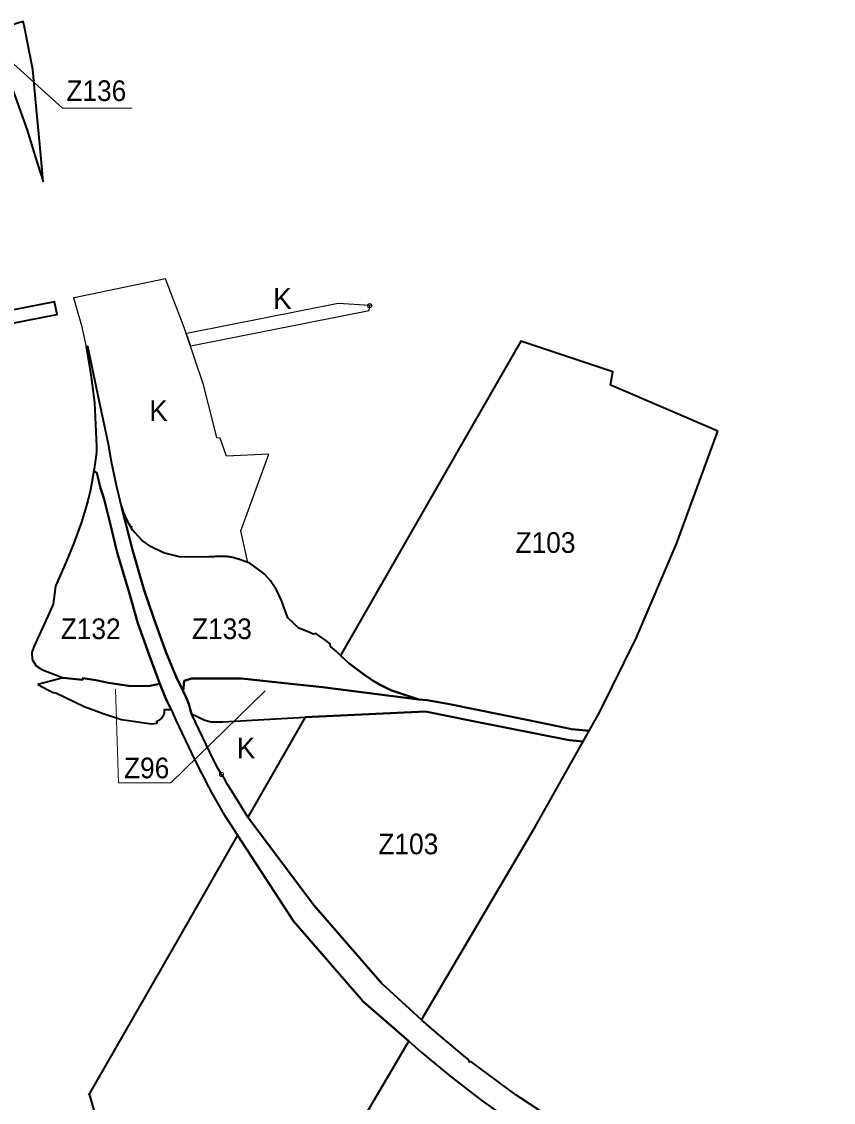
# Model space of a CAD drawing. Extents: x -650276 to -642489, y -1074311 to -1066658.
# Drawn here: x -647869 to -646927, y -1068210 to -1066956 of the extents above; entities that cross this region are included whole.
import ezdxf

# ---------------------------------------------------------------- set-up
doc = ezdxf.new("R2010")
doc.units = 0
doc.header["$LTSCALE"] = 9.6
doc.header["$PDMODE"] = 32
doc.header["$PDSIZE"] = 4.8
for name, color, linetype, lineweight in [('4', 7, 'Continuous', 40), ('41', 7, 'Continuous', 25), ('44', 7, 'Continuous', 40), ('45', 7, 'Continuous', 40), ('46', 7, 'Continuous', 13), ('47', 7, 'Continuous', 13), ('48', 7, 'Continuous', 35), ('59', 7, 'Continuous', 13)]:
    doc.layers.add(name, color=color, linetype=linetype, lineweight=lineweight)
doc.layers.add('43', color=7, linetype='Continuous')

msp = doc.modelspace()

# ---------------------------------------------------------------- linework, layer by layer
at = {"layer": '4'}
msp.add_lwpolyline([(-647876.57, -1067043.5), (-647863.04, -1067081.36), (-647853.65, -1067111.91), (-647844.3, -1067141.25), (-647847.09, -1067110.58), (-647850.07, -1067077.71), (-647852.63, -1067049.52), (-647856.11, -1067011.21), (-647866.14, -1066961.98), (-647867.46, -1066955.52), (-647905.28, -1066967.07), (-647903.5, -1066972.05)], close=True, dxfattribs=at)
at = {"layer": '41'}
for p, q in [((-647740.124, -1067546.265), (-647739.417, -1067547.032)), ((-647740, -1067546.181), (-647739.998, -1067546.18)), ((-647640.591, -1067576.33), (-647640.087, -1067576.306))]:
    msp.add_line(p, q, dxfattribs=at)
for points in [[(-647638.68, -1067439.06), (-647642.686, -1067438.46), (-647645.78, -1067425.81), (-647658.13, -1067376.99), (-647680.64, -1067310.37), (-647702.42, -1067253.98), (-647808.25, -1067276.11), (-647809.02, -1067276.27), (-647804.823, -1067290.788)], [(-647465.203, -1067285.115), (-647501.968, -1067282.642), (-647673.685, -1067316.666), (-647678.21, -1067317.562), (-647673.367, -1067331.895), (-647670.77, -1067331.38), (-647501.099, -1067297.762)], [(-647501.099, -1067297.762), (-647465.699, -1067290.747), (-647465.203, -1067285.115)], [(-647804.823, -1067290.788), (-647799.76, -1067308.3), (-647794.54, -1067333.14)], [(-647794.54, -1067333.14), (-647792.52, -1067332.74), (-647778.78, -1067397.1), (-647768.5, -1067446.04)], [(-647768.5, -1067446.04), (-647764.89, -1067466.64), (-647759.16, -1067494.01), (-647756.55, -1067505.32), (-647755.255, -1067510.676)], [(-647615.048, -1067580.385), (-647606.559, -1067583.309), (-647614.75, -1067546.53), (-647582.2, -1067457.65), (-647631.59, -1067459.72), (-647638.68, -1067439.06)], [(-647755.255, -1067510.676), (-647755.159, -1067511.027), (-647754.116, -1067514.604)], [(-647754.116, -1067514.604), (-647753.006, -1067518.156), (-647751.818, -1067521.68), (-647750.545, -1067525.169), (-647749.178, -1067528.619), (-647747.708, -1067532.022), (-647746.127, -1067535.371), (-647744.43, -1067538.658), (-647740.122, -1067546.264)], [(-647742.158, -1067541.404), (-647741.902, -1067541.247), (-647741.647, -1067541.09), (-647740.804, -1067541.512), (-647742.167, -1067542.348)], [(-647739.998, -1067546.18), (-647742.045, -1067542.565), (-647742.167, -1067542.348), (-647742.158, -1067541.404)], [(-647742.167, -1067542.348), (-647742.037, -1067542.56), (-647741.936, -1067542.723), (-647741.743, -1067543.03), (-647741.67, -1067543.146), (-647741.447, -1067543.497), (-647741.402, -1067543.568), (-647741.148, -1067543.963), (-647741.132, -1067543.989), (-647740.859, -1067544.408), (-647740.846, -1067544.427), (-647740.583, -1067544.825), (-647740.541, -1067544.889), (-647740.519, -1067544.919), (-647740.333, -1067545.195), (-647740.265, -1067545.295), (-647740.068, -1067545.582), (-647739.971, -1067545.724), (-647739.801, -1067545.968), (-647739.674, -1067546.15), (-647739.532, -1067546.353), (-647739.504, -1067546.391), (-647739.374, -1067546.575), (-647739.26, -1067546.736), (-647739.072, -1067546.998), (-647738.986, -1067547.117), (-647738.767, -1067547.418), (-647738.709, -1067547.496), (-647738.456, -1067547.839), (-647738.431, -1067547.874), (-647738.148, -1067548.252), (-647737.867, -1067548.624), (-647737.834, -1067548.667), (-647737.581, -1067548.996), (-647737.518, -1067549.078)], [(-647739.966, -1067546.23), (-647739.968, -1067546.231), (-647739.983, -1067546.206)], [(-647737.525, -1067549.085), (-647729.802, -1067557.462), (-647719.661, -1067564.884), (-647704.458, -1067572.034), (-647685.968, -1067576.68)], [(-647685.968, -1067576.68), (-647654.743, -1067576.996), (-647651.965, -1067576.865)], [(-647651.965, -1067576.865), (-647651.711, -1067576.853), (-647651.205, -1067576.828), (-647650.7, -1067576.803), (-647650.194, -1067576.778), (-647649.689, -1067576.752), (-647649.183, -1067576.727), (-647648.677, -1067576.701), (-647648.172, -1067576.675), (-647647.897, -1067576.661), (-647647.666, -1067576.65), (-647647.161, -1067576.624), (-647646.655, -1067576.598), (-647646.149, -1067576.572), (-647645.644, -1067576.546), (-647645.138, -1067576.521), (-647644.899, -1067576.509), (-647644.633, -1067576.496), (-647644.127, -1067576.471), (-647643.622, -1067576.447), (-647643.117, -1067576.424), (-647642.611, -1067576.401), (-647642.106, -1067576.38), (-647641.901, -1067576.371), (-647641.601, -1067576.359), (-647641.096, -1067576.34), (-647640.592, -1067576.322)], [(-647640.087, -1067576.306), (-647639.583, -1067576.291), (-647639.078, -1067576.278), (-647638.902, -1067576.275), (-647638.574, -1067576.267), (-647638.071, -1067576.258), (-647637.567, -1067576.251), (-647637.064, -1067576.246), (-647637.01, -1067576.246), (-647636.419, -1067576.254), (-647635.902, -1067576.265), (-647635.757, -1067576.268), (-647635.094, -1067576.286), (-647635.037, -1067576.288), (-647634.431, -1067576.309), (-647633.767, -1067576.337), (-647633.102, -1067576.37), (-647633.058, -1067576.372), (-647632.9, -1067576.382), (-647632.437, -1067576.408), (-647631.772, -1067576.452), (-647631.106, -1067576.502), (-647631.076, -1067576.504), (-647630.44, -1067576.557), (-647629.896, -1067576.607), (-647629.774, -1067576.618), (-647629.107, -1067576.685), (-647629.091, -1067576.687), (-647628.441, -1067576.759), (-647627.775, -1067576.839), (-647627.107, -1067576.926), (-647626.443, -1067577.019), (-647625.783, -1067577.139), (-647625.14, -1067577.282), (-647625.129, -1067577.284), (-647624.476, -1067577.436), (-647623.824, -1067577.594), (-647623.199, -1067577.752), (-647623.174, -1067577.759), (-647622.525, -1067577.929), (-647621.877, -1067578.106), (-647621.269, -1067578.278), (-647621.23, -1067578.289), (-647620.586, -1067578.478), (-647619.942, -1067578.674), (-647619.352, -1067578.859), (-647619.301, -1067578.875), (-647618.661, -1067579.083), (-647618.023, -1067579.297), (-647617.451, -1067579.494), (-647617.387, -1067579.517), (-647616.752, -1067579.743), (-647616.12, -1067579.975), (-647615.566, -1067580.184), (-647615.489, -1067580.214), (-647615.048, -1067580.385)]]:
    msp.add_lwpolyline(points, dxfattribs=at)
for start, end in [(214.04927, 214.0695), (214.08975, 214.75472)]:
    msp.add_arc((-647670.608, -1067499.289), 83.75, start, end, dxfattribs=at)
msp.add_point((-647465.203, -1067285.115), dxfattribs=at)
at = {"layer": '44'}
for p, q in [((-647489.3, -1067700.07), (-647474.13, -1067711.81)), ((-647540.208, -1067762.876), (-647400.63, -1067756.19))]:
    msp.add_line(p, q, dxfattribs=at)
for points in [[(-647606.818, -1067879.061), (-647617.25, -1067861.95), (-647625.37, -1067848.86), (-647630.3, -1067841.02), (-647633.69, -1067834.31), (-647637.21, -1067829.29), (-647642.29, -1067820.76), (-647650.8, -1067803.28), (-647672.05, -1067758.98), (-647673.47, -1067753.48), (-647673.47, -1067753.48), (-647674.67, -1067748.73), (-647676.47, -1067744.5), (-647678.66, -1067739.38), (-647681.91, -1067732.74), (-647690.09, -1067716.05), (-647702.04, -1067686.86), (-647715.92, -1067648.12), (-647727.37, -1067614.33), (-647740.49, -1067568.67), (-647751.41, -1067526.58), (-647756.55, -1067505.32), (-647759.16, -1067494.01), (-647764.89, -1067466.64), (-647768.5, -1067446.04), (-647778.78, -1067397.1), (-647792.52, -1067332.74), (-647794.54, -1067333.14), (-647788.77, -1067365.03), (-647784.55, -1067398.01), (-647782.39, -1067448.34), (-647782.5, -1067455.11), (-647784.36, -1067469.6), (-647785.64, -1067477.02), (-647781.85, -1067479.19), (-647777.55, -1067496.95), (-647773.96, -1067508.48), (-647768.5, -1067529.75), (-647758.25, -1067571.79), (-647744.61, -1067617.96), (-647734.63, -1067652.57), (-647721.05, -1067691.73), (-647708.71, -1067723.99), (-647702.21, -1067740.43), (-647699.89, -1067745.24), (-647697.85, -1067749.46), (-647695.71, -1067753.9), (-647690.19, -1067766.37), (-647668.13, -1067812.76), (-647651.94, -1067844.36), (-647648.33, -1067851.17), (-647643.83, -1067859.13), (-647635.77, -1067873.43), (-647618.773, -1067899.914)], [(-647185.93, -1067377.38), (-647183.09, -1067362.16), (-647289.924, -1067326.309), (-647364.024, -1067455.561), (-647499.095, -1067691.163), (-647489.3, -1067700.07)], [(-647061.252, -1067430.908), (-647181.878, -1067379.12), (-647185.93, -1067377.38)], [(-647155.592, -1067670.17), (-647108.971, -1067561.55), (-647061.252, -1067430.908)], [(-647210.537, -1067778.594), (-647198.088, -1067756.5), (-647155.592, -1067670.17)], [(-647695.797, -1067753.719), (-647697.85, -1067749.46), (-647699.89, -1067745.24), (-647702.21, -1067740.43), (-647708.71, -1067723.99), (-647720.45, -1067726.49), (-647732.71, -1067727.02), (-647745.41, -1067726.6), (-647768.53, -1067722.82), (-647783.13, -1067719.68), (-647798.17, -1067717.58), (-647798.5, -1067719.67), (-647821.02, -1067717.33), (-647850.45, -1067724.77)], [(-647520.145, -1067727.879), (-647557, -1067724), (-647614, -1067718), (-647643, -1067718), (-647672, -1067718), (-647680.804, -1067720.745), (-647681.91, -1067732.74)], [(-647474.13, -1067711.81), (-647462.45, -1067719.84), (-647453.87, -1067724.97), (-647440.81, -1067731.38), (-647408.2, -1067742.37), (-647398.74, -1067743.15)], [(-647850.45, -1067724.77), (-647838.18, -1067731.62), (-647832.56, -1067734.22), (-647829.49, -1067734.58), (-647796.87, -1067750.25), (-647774.54, -1067758.68), (-647753.53, -1067765.58), (-647718.54, -1067770.6), (-647712.01, -1067769.63), (-647712.26, -1067767.28)], [(-647681.91, -1067732.74), (-647678.66, -1067739.38), (-647676.47, -1067744.5), (-647674.67, -1067748.73), (-647673.47, -1067753.48)], [(-647398.74, -1067743.15), (-647408.2, -1067742.37), (-647520.145, -1067727.879)], [(-647210.537, -1067778.594), (-647213.92, -1067778.26), (-647231.17, -1067776.55), (-647237.91, -1067775.18), (-647280.78, -1067766.44), (-647374.55, -1067747.34), (-647398.74, -1067743.15)], [(-647398.74, -1067743.15), (-647374.55, -1067747.34), (-647280.78, -1067766.44), (-647237.91, -1067775.18), (-647231.17, -1067776.55), (-647213.92, -1067778.26), (-647210.537, -1067778.594)], [(-647712.26, -1067767.28), (-647711.773, -1067767.135), (-647711.286, -1067766.968), (-647710.799, -1067766.777), (-647710.315, -1067766.562), (-647709.834, -1067766.324), (-647709.359, -1067766.062), (-647708.892, -1067765.776), (-647708.433, -1067765.466), (-647707.985, -1067765.133), (-647707.55, -1067764.777), (-647707.128, -1067764.398), (-647706.723, -1067763.999), (-647706.335, -1067763.579), (-647705.966, -1067763.14), (-647705.617, -1067762.683), (-647705.29, -1067762.21), (-647704.985, -1067761.721), (-647704.704, -1067761.22), (-647704.447, -1067760.707), (-647704.216, -1067760.184), (-647704.01, -1067759.653), (-647703.83, -1067759.117), (-647703.675, -1067758.576), (-647703.547, -1067758.033), (-647703.445, -1067757.489), (-647703.368, -1067756.946), (-647703.315, -1067756.406), (-647703.287, -1067755.87), (-647703.282, -1067755.341), (-647703.3, -1067754.818), (-647703.34, -1067754.304), (-647703.4, -1067753.8), (-647695.797, -1067753.719)], [(-647673.47, -1067753.48), (-647672.05, -1067758.98), (-647672.05, -1067758.98), (-647656.469, -1067766.309), (-647649.22, -1067768.38), (-647635.758, -1067768.38), (-647540.208, -1067762.876)], [(-647217.611, -1067791.149), (-647233.83, -1067789.69), (-647345.11, -1067767.28), (-647400.63, -1067756.19), (-647540.208, -1067762.876)], [(-647400.63, -1067756.19), (-647345.11, -1067767.28), (-647233.83, -1067789.69), (-647217.611, -1067791.149), (-647210.537, -1067778.594)], [(-647540.208, -1067762.876), (-647593.267, -1067855.425), (-647606.818, -1067879.061)], [(-647405.026, -1068113.904), (-647273.297, -1067889.981), (-647217.611, -1067791.149)], [(-647405.026, -1068113.904), (-647451.024, -1068071.886), (-647530.038, -1067980.839), (-647606.818, -1067879.061)], [(-647606.818, -1067879.061), (-647530.038, -1067980.839), (-647451.024, -1068071.886), (-647405.026, -1068113.904)], [(-647618.773, -1067899.914), (-647685.819, -1068016.861), (-647781.346, -1068183.485), (-647791.669, -1068201.583)], [(-647781.204, -1068756.329), (-647675.054, -1068572.919), (-647461.188, -1068209.373), (-647419.713, -1068138.871), (-647472.338, -1068093.096), (-647553.628, -1067999.427), (-647618.773, -1067899.915), (-647618.773, -1067899.914)], [(-647618.773, -1067899.914), (-647553.628, -1067999.427), (-647472.338, -1068093.096), (-647419.713, -1068138.871)], [(-647246.8, -1068233.08), (-647295.47, -1068201.09), (-647347.74, -1068162.54), (-647349.59, -1068163.24), (-647350.6, -1068160.26), (-647353.81, -1068157.67), (-647385.13, -1068131.51), (-647405.026, -1068113.904)], [(-647419.713, -1068138.871), (-647405.71, -1068151.74), (-647372.38, -1068179.01), (-647337.74, -1068205.67), (-647334.62, -1068208.02), (-647307.39, -1068227.44), (-647281.64, -1068244.34), (-647234.11, -1068273.04), (-647230.83, -1068274.93), (-647174.56, -1068306.35), (-647142.788, -1068322.462), (-647130.29, -1068328.8), (-647079.16, -1068357.01), (-647032.91, -1068382.51), (-647029.23, -1068384.46), (-646997.06, -1068401.37), (-646929.56, -1068435.42), (-646927.06, -1068436.66)], [(-647791.055, -1068200.507), (-647765.22, -1068287.94), (-647758.45, -1068317.66), (-647756.09, -1068337.61), (-647754.99, -1068378.21), (-647757.41, -1068419.98), (-647760.22, -1068463.96), (-647768.02, -1068570.36), (-647772.85, -1068656.41), (-647778.967, -1068752.463)]]:
    msp.add_lwpolyline(points, dxfattribs=at)
at = {"layer": '44', "lineweight": 13}
msp.add_lwpolyline([(-647586.774, -1067732.166), (-647696.17, -1067839.096), (-647756.708, -1067839.096), (-647760.132, -1067730.33)], dxfattribs=at)
at = {"layer": '45'}
for points in [[(-647708.71, -1067723.99), (-647721.05, -1067691.73), (-647734.63, -1067652.57), (-647744.61, -1067617.96), (-647758.25, -1067571.79), (-647768.5, -1067529.75), (-647773.96, -1067508.48), (-647777.55, -1067496.95), (-647781.85, -1067479.19), (-647785.64, -1067477.02), (-647789.39, -1067498.84), (-647792.54, -1067511.85), (-647799.39, -1067535.48)], [(-647799.39, -1067535.48), (-647808.71, -1067561.03), (-647817.59, -1067582.4)], [(-647739.417, -1067547.032), (-647740.122, -1067546.264), (-647744.43, -1067538.658), (-647751.41, -1067526.58), (-647740.49, -1067568.67), (-647727.37, -1067614.33), (-647715.92, -1067648.12)], [(-647737.867, -1067548.624), (-647738.148, -1067548.252), (-647738.514, -1067547.9), (-647739.417, -1067547.032)], [(-647650.7, -1067576.803), (-647651.205, -1067576.828), (-647651.711, -1067576.853), (-647651.965, -1067576.865), (-647654.743, -1067576.996), (-647685.968, -1067576.68), (-647704.458, -1067572.034), (-647719.661, -1067564.884), (-647729.802, -1067557.462), (-647737.581, -1067548.996), (-647737.867, -1067548.624)], [(-647817.59, -1067582.4), (-647829.97, -1067610.62), (-647832.8, -1067631.53), (-647835.06, -1067637.01), (-647855.24, -1067681.26), (-647857.51, -1067687.74), (-647856.9, -1067695.97)], [(-647647.161, -1067576.624), (-647647.666, -1067576.65), (-647647.897, -1067576.661), (-647648.172, -1067576.675), (-647648.677, -1067576.701), (-647649.183, -1067576.727), (-647649.689, -1067576.752), (-647650.194, -1067576.778), (-647650.7, -1067576.803)], [(-647646.149, -1067576.572), (-647646.655, -1067576.598), (-647647.161, -1067576.624)], [(-647644.633, -1067576.496), (-647644.899, -1067576.509), (-647645.138, -1067576.521), (-647645.644, -1067576.546), (-647646.149, -1067576.572)], [(-647643.117, -1067576.424), (-647643.622, -1067576.447), (-647644.127, -1067576.471), (-647644.633, -1067576.496)], [(-647640.592, -1067576.322), (-647641.096, -1067576.34), (-647641.601, -1067576.359), (-647641.901, -1067576.371), (-647642.106, -1067576.38), (-647642.611, -1067576.401), (-647643.117, -1067576.424)], [(-647639.583, -1067576.291), (-647640.087, -1067576.306), (-647640.592, -1067576.322)], [(-647638.902, -1067576.275), (-647639.078, -1067576.278), (-647639.583, -1067576.291)], [(-647632.437, -1067576.408), (-647632.9, -1067576.39), (-647633.102, -1067576.383), (-647633.767, -1067576.357), (-647634.431, -1067576.331), (-647635.095, -1067576.305), (-647635.757, -1067576.28), (-647635.902, -1067576.274), (-647636.419, -1067576.254), (-647637.064, -1067576.246), (-647637.567, -1067576.251), (-647638.071, -1067576.258), (-647638.574, -1067576.267), (-647638.902, -1067576.275)], [(-647629.774, -1067576.618), (-647629.896, -1067576.607), (-647630.44, -1067576.557), (-647631.106, -1067576.502), (-647631.772, -1067576.452), (-647632.437, -1067576.408)], [(-647628.441, -1067576.759), (-647629.107, -1067576.685), (-647629.774, -1067576.618)], [(-647623.199, -1067577.752), (-647623.824, -1067577.594), (-647624.481, -1067577.461), (-647625.149, -1067577.324), (-647625.794, -1067577.193), (-647626.451, -1067577.059), (-647627.107, -1067576.926), (-647627.775, -1067576.839), (-647628.441, -1067576.759)], [(-647621.269, -1067578.278), (-647621.877, -1067578.106), (-647622.525, -1067577.929), (-647623.199, -1067577.752)], [(-647619.352, -1067578.859), (-647619.942, -1067578.674), (-647620.586, -1067578.478), (-647621.269, -1067578.278)], [(-647615.048, -1067580.385), (-647615.566, -1067580.184), (-647616.12, -1067579.975), (-647616.752, -1067579.743), (-647617.451, -1067579.494), (-647618.023, -1067579.297), (-647618.661, -1067579.083), (-647619.352, -1067578.859)], [(-647547.663, -1067659.519), (-647560.187, -1067647.458), (-647567.744, -1067627.24), (-647573.605, -1067614.951), (-647580.539, -1067604.432), (-647586.864, -1067597.411), (-647591.227, -1067593.613), (-647604.415, -1067584.047), (-647606.559, -1067583.309), (-647615.048, -1067580.385)], [(-647715.92, -1067648.12), (-647702.04, -1067686.86), (-647690.09, -1067716.05), (-647681.91, -1067732.74), (-647680.804, -1067720.745), (-647672, -1067718), (-647643, -1067718), (-647614, -1067718), (-647557, -1067724), (-647520.145, -1067727.879), (-647408.2, -1067742.37), (-647440.81, -1067731.38), (-647453.87, -1067724.97), (-647462.45, -1067719.84), (-647474.13, -1067711.81), (-647489.3, -1067700.07), (-647499.095, -1067691.163)], [(-647499.095, -1067691.163), (-647503.97, -1067686.73), (-647510.6, -1067680.86), (-647511.24, -1067677.53), (-647517.74, -1067672.85), (-647520.13, -1067671.13), (-647527.76, -1067665.65), (-647530.82, -1067666.65), (-647536.83, -1067663.64), (-647547.663, -1067659.519)], [(-647856.9, -1067695.97), (-647852.3, -1067703.36), (-647845.74, -1067707.59), (-647821.02, -1067717.33)], [(-647821.02, -1067717.33), (-647798.5, -1067719.67), (-647798.17, -1067717.58), (-647783.13, -1067719.68), (-647768.53, -1067722.82), (-647745.41, -1067726.6), (-647732.71, -1067727.02), (-647720.45, -1067726.49), (-647708.71, -1067723.99)]]:
    msp.add_lwpolyline(points, dxfattribs=at)
at = {"layer": '47'}
msp.add_lwpolyline([(-647606.818, -1067879.061), (-647540.208, -1067762.876), (-647635.758, -1067768.38), (-647649.22, -1067768.38), (-647656.469, -1067766.309), (-647672.05, -1067758.98), (-647650.8, -1067803.28), (-647642.29, -1067820.76), (-647637.21, -1067829.29), (-647633.69, -1067834.31), (-647630.3, -1067841.02), (-647625.37, -1067848.86), (-647617.25, -1067861.95)], close=True, dxfattribs=at)
msp.add_point((-647637.21, -1067829.29), dxfattribs=at)
at = {"layer": '48'}
msp.add_lwpolyline([(-647882.66, -1067529.231), (-647926.759, -1067358.379), (-647937.355, -1067316.774), (-647828.376, -1067295.406), (-647828.104, -1067295.352), (-647831.28, -1067280.69), (-647948.488, -1067303.671)], dxfattribs=at)
at = {"layer": '59'}
msp.add_lwpolyline([(-647740.809, -1067055.795), (-647821.729, -1067055.795), (-647882.822, -1067000.815)], dxfattribs=at)

# ---------------------------------------------------------------- texts
at = {"layer": '43'}
for p in [(-647577.244, -1067288.889), (-647721.126, -1067419.035)]:
    msp.add_text('K', height=24, dxfattribs=at).set_placement(p)
at = {"layer": '44', "width": 0.95}
for s, p in [('Z103', (-647295.975, -1067572.121)), ('Z103', (-647295.975, -1067572.121)), ('Z96', (-647750.408, -1067833.749)), ('Z103', (-647455.179, -1067921.933)), ('Z103', (-647455.179, -1067921.933))]:
    msp.add_text(s, height=24, dxfattribs=at).set_placement(p)
at = {"layer": '46', "width": 0.95}
for s, p in [('Z132', (-647823.879, -1067672.215)), ('Z133', (-647671.579, -1067672.215))]:
    msp.add_text(s, height=24, dxfattribs=at).set_placement(p)
at = {"layer": '48'}
msp.add_text('K', height=24, dxfattribs=at).set_placement((-647619.44, -1067810.434))
at = {"layer": '59', "width": 0.95}
msp.add_text('Z136', height=24, dxfattribs=at).set_placement((-647817.317, -1067047.713))

doc.saveas('drawing.dxf')
